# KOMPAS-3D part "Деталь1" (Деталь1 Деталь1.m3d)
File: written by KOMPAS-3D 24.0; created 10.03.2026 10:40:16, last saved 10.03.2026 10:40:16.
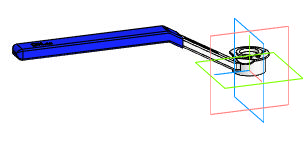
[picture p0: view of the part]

Document properties: Автор: R2D2; Полное имя файла: C:\Users\R2D2\Downloads\Деталь1 Деталь1.m3d

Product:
- Body: Твердое тело1  | qty 1
- Part/product: Деталь1
    additional columns: Типовые

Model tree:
1. Твердое тело1  (labels: Твердое тело1)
